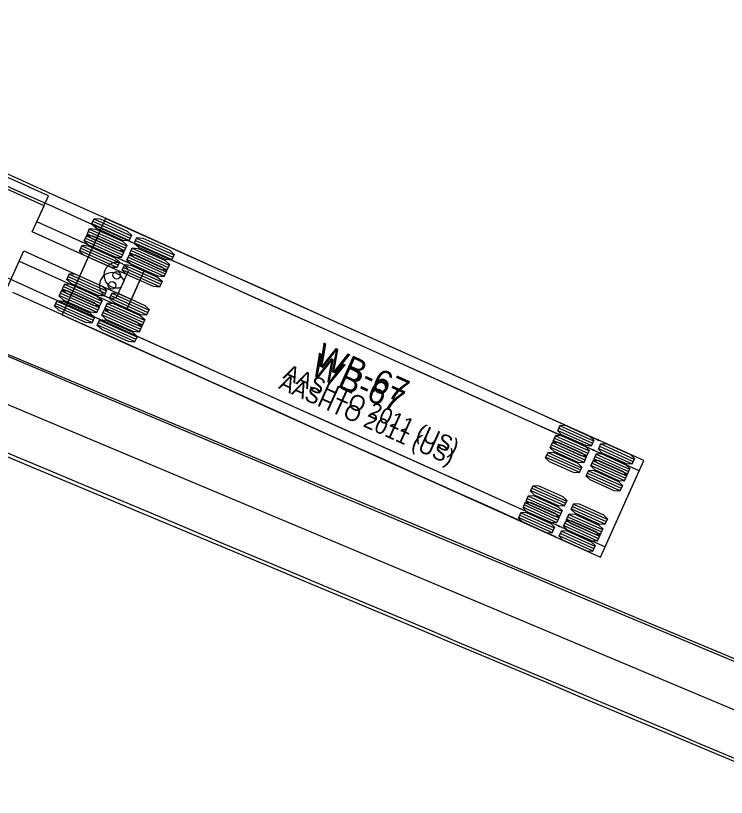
# Model space of a CAD drawing. Extents: x 916040 to 917457, y 328936 to 330267.
# Drawn here: x 917146.2 to 917210, y 329502 to 329572.2 of the extents above; entities that cross this region are included whole.
import ezdxf

# ---------------------------------------------------------------- set-up
doc = ezdxf.new("R2010")
doc.units = 0
for name, color, linetype in [('NB_RightontoRoute25_WB67', 7, 'Continuous'), ('NB_ThruontoManchester_WB67', 7, 'Continuous'), ('WB_LeftontoSaco_WB67', 7, 'Continuous'), ('WB_RightontoManchester_WB67', 7, 'Continuous'), ('WB_Thru_WB67', 7, 'Continuous')]:
    doc.layers.add(name, color=color, linetype=linetype)

msp = doc.modelspace()

# ---------------------------------------------------------------- linework, layer by layer
at = {"layer": 'NB_RightontoRoute25_WB67'}
msp.add_line((917062.28, 329572.242), (917451.537, 329408.712), dxfattribs=at)
for points in [[(917143.156, 329542.604), (917146.231, 329541.313), (917149.306, 329540.021), (917152.38, 329538.729), (917155.455, 329537.437), (917158.53, 329536.146), (917161.604, 329534.854), (917164.679, 329533.562), (917167.754, 329532.271), (917170.829, 329530.979), (917173.903, 329529.687), (917176.978, 329528.395), (917180.053, 329527.104), (917183.128, 329525.812), (917186.202, 329524.52), (917189.277, 329523.229), (917192.352, 329521.937), (917195.426, 329520.645), (917198.501, 329519.353), (917201.576, 329518.062), (917204.651, 329516.77), (917207.725, 329515.478), (917210.8, 329514.187)], [(917144.777, 329542.093), (917147.854, 329540.807), (917150.932, 329539.521), (917154.009, 329538.234), (917157.087, 329536.947), (917160.164, 329535.66), (917163.24, 329534.372), (917166.317, 329533.084), (917169.394, 329531.796), (917172.47, 329530.508), (917175.547, 329529.219), (917178.623, 329527.93), (917181.699, 329526.641), (917184.775, 329525.352), (917187.851, 329524.062), (917190.927, 329522.773), (917194.002, 329521.483), (917197.078, 329520.193), (917200.154, 329518.903), (917203.229, 329517.613), (917206.305, 329516.323), (917209.38, 329515.032), (917212.455, 329513.742)], [(917143.133, 329533.937), (917146.208, 329532.645), (917149.282, 329531.353), (917152.357, 329530.062), (917155.432, 329528.77), (917158.506, 329527.478), (917161.581, 329526.187), (917164.656, 329524.895), (917167.73, 329523.603), (917170.805, 329522.311), (917173.88, 329521.02), (917176.954, 329519.728), (917180.029, 329518.436), (917183.104, 329517.145), (917186.179, 329515.853), (917189.253, 329514.561), (917192.328, 329513.27), (917195.403, 329511.978), (917198.477, 329510.686), (917201.552, 329509.394), (917204.627, 329508.103), (917207.701, 329506.811), (917210.776, 329505.519)], [(917144.577, 329532.964), (917147.654, 329531.679), (917150.73, 329530.392), (917153.806, 329529.106), (917156.883, 329527.819), (917159.959, 329526.531), (917163.035, 329525.244), (917166.111, 329523.956), (917169.186, 329522.668), (917172.262, 329521.379), (917175.338, 329520.091), (917178.413, 329518.802), (917181.489, 329517.513), (917184.564, 329516.223), (917187.64, 329514.934), (917190.715, 329513.644), (917193.79, 329512.355), (917196.866, 329511.065), (917199.941, 329509.775), (917203.016, 329508.485), (917206.091, 329507.194), (917209.166, 329505.904), (917212.242, 329504.614)]]:
    msp.add_lwpolyline(points, dxfattribs=at)
at = {"layer": 'NB_ThruontoManchester_WB67'}
msp.add_line((917062.28, 329572.242), (917451.537, 329408.712), dxfattribs=at)
at = {"layer": 'WB_LeftontoSaco_WB67'}
for p, q in [((917148.719, 329555.149), (917135.042, 329561.308)), ((917147.665, 329552.809), (917148.719, 329555.149)), ((917157.33, 329548.457), (917147.665, 329552.809)), ((917153.837, 329553.119), (917150.347, 329545.368)), ((917152.601, 329552.647), (917155.944, 329551.142)), ((917152.695, 329552.856), (917156.038, 329551.351)), ((917152.789, 329553.065), (917156.132, 329551.56)), ((917202.163, 329531.358), (917153.837, 329553.119)), ((917152.017, 329551.352), (917155.361, 329549.846)), ((917152.111, 329551.561), (917155.455, 329550.055)), ((917156.618, 329551.341), (917159.962, 329549.835)), ((917151.923, 329551.143), (917155.266, 329549.637)), ((917156.43, 329550.923), (917159.774, 329549.417)), ((917156.524, 329551.132), (917159.868, 329549.626)), ((917145.434, 329547.855), (917146.488, 329550.195)), ((917146.488, 329550.195), (917156.153, 329545.843)), ((917155.941, 329549.836), (917159.284, 329548.331)), ((917155.753, 329549.418), (917159.096, 329547.913)), ((917155.847, 329549.627), (917159.19, 329548.122)), ((917155.232, 329546.943), (917155.896, 329548.417)), ((917156.153, 329545.843), (917157.33, 329548.457)), ((917150.37, 329547.693), (917153.713, 329546.188)), ((917150.464, 329547.902), (917153.807, 329546.397)), ((917150.558, 329548.111), (917153.901, 329546.606)), ((917149.786, 329546.398), (917153.13, 329544.892)), ((917149.88, 329546.606), (917153.224, 329545.101)), ((917154.388, 329546.387), (917157.731, 329544.881)), ((917149.692, 329546.189), (917153.036, 329544.683)), ((917154.199, 329545.969), (917157.543, 329544.463)), ((917154.293, 329546.178), (917157.637, 329544.672)), ((917150.347, 329545.368), (917198.673, 329523.607)), ((917150.347, 329545.368), (917150.347, 329545.368)), ((917153.71, 329544.882), (917157.053, 329543.377)), ((917153.522, 329544.464), (917156.865, 329542.959)), ((917153.616, 329544.673), (917156.959, 329543.168)), ((917194.638, 329534.495), (917197.647, 329533.14)), ((917194.45, 329534.077), (917197.459, 329532.722)), ((917194.544, 329534.286), (917197.553, 329532.931)), ((917193.96, 329532.991), (917196.969, 329531.636)), ((917193.772, 329532.573), (917196.781, 329531.218)), ((917193.866, 329532.782), (917196.875, 329531.427)), ((917198.097, 329532.435), (917201.106, 329531.08)), ((917198.191, 329532.644), (917201.2, 329531.289)), ((917198.285, 329532.853), (917201.294, 329531.498)), ((917197.419, 329530.93), (917200.428, 329529.576)), ((917197.513, 329531.139), (917200.522, 329529.785)), ((917197.608, 329531.348), (917200.617, 329529.993)), ((917198.673, 329523.607), (917202.163, 329531.358)), ((917192.107, 329528.876), (917195.116, 329527.521)), ((917192.202, 329529.085), (917195.211, 329527.73)), ((917192.013, 329528.667), (917195.022, 329527.312)), ((917191.43, 329527.372), (917194.439, 329526.017)), ((917191.524, 329527.581), (917194.533, 329526.226)), ((917195.849, 329527.443), (917198.858, 329526.088)), ((917191.336, 329527.163), (917194.345, 329525.808)), ((917195.661, 329527.025), (917198.67, 329525.67)), ((917195.755, 329527.234), (917198.764, 329525.879)), ((917195.171, 329525.938), (917198.18, 329524.583)), ((917194.983, 329525.52), (917197.992, 329524.165)), ((917195.077, 329525.729), (917198.086, 329524.374))]:
    msp.add_line(p, q, dxfattribs=at)
for points in [[(917198.06, 329533.206), (917195.019, 329534.575), (917191.978, 329535.944), (917188.937, 329537.314), (917185.896, 329538.683), (917182.855, 329540.052), (917179.814, 329541.422), (917176.773, 329542.791), (917173.732, 329544.16), (917170.691, 329545.53), (917167.65, 329546.899), (917164.609, 329548.268), (917161.568, 329549.638), (917158.526, 329551.007), (917155.485, 329552.376), (917152.444, 329553.746), (917149.403, 329555.115), (917146.362, 329556.484), (917143.321, 329557.854)], [(917194.57, 329525.455), (917191.529, 329526.824), (917188.488, 329528.194), (917185.447, 329529.563), (917182.406, 329530.932), (917179.365, 329532.302), (917176.324, 329533.671), (917173.283, 329535.041), (917170.242, 329536.41), (917167.201, 329537.779), (917164.16, 329539.149), (917161.119, 329540.518), (917158.078, 329541.887), (917155.037, 329543.257), (917151.995, 329544.626), (917148.954, 329545.995), (917145.913, 329547.365)]]:
    msp.add_lwpolyline(points, dxfattribs=at)
for points in [[(917152.577, 329552.595), (917152.812, 329553.117), (917153.351, 329553.063), (917155.758, 329551.979), (917156.155, 329551.612), (917155.921, 329551.09), (917155.382, 329551.144), (917152.975, 329552.228)], [(917151.9, 329551.091), (917152.135, 329551.613), (917152.673, 329551.559), (917155.081, 329550.475), (917155.478, 329550.107), (917155.243, 329549.585), (917154.704, 329549.639), (917152.297, 329550.723)], [(917156.407, 329550.871), (917156.642, 329551.393), (917157.181, 329551.339), (917159.588, 329550.255), (917159.985, 329549.887), (917159.75, 329549.366), (917159.211, 329549.419), (917156.804, 329550.503)], [(917155.729, 329549.367), (917155.964, 329549.888), (917156.503, 329549.834), (917158.91, 329548.751), (917159.308, 329548.383), (917159.073, 329547.861), (917158.534, 329547.915), (917156.127, 329548.999)], [(917150.346, 329547.641), (917150.581, 329548.163), (917151.12, 329548.109), (917153.527, 329547.025), (917153.925, 329546.657), (917153.69, 329546.136), (917153.151, 329546.189), (917150.744, 329547.273)], [(917149.669, 329546.137), (917149.904, 329546.658), (917150.443, 329546.605), (917152.85, 329545.521), (917153.247, 329545.153), (917153.012, 329544.631), (917152.473, 329544.685), (917150.066, 329545.769)], [(917154.176, 329545.917), (917154.411, 329546.438), (917154.95, 329546.385), (917157.357, 329545.301), (917157.754, 329544.933), (917157.519, 329544.411), (917156.981, 329544.465), (917154.573, 329545.549)], [(917153.499, 329544.412), (917153.733, 329544.934), (917154.272, 329544.88), (917156.679, 329543.796), (917157.077, 329543.428), (917156.842, 329542.907), (917156.303, 329542.96), (917153.896, 329544.044)], [(917194.426, 329534.026), (917194.661, 329534.547), (917195.153, 329534.515), (917197.32, 329533.539), (917197.67, 329533.192), (917197.435, 329532.671), (917196.943, 329532.703), (917194.777, 329533.679)], [(917193.749, 329532.521), (917193.984, 329533.043), (917194.476, 329533.01), (917196.642, 329532.034), (917196.993, 329531.688), (917196.758, 329531.166), (917196.266, 329531.199), (917194.099, 329532.174)], [(917198.073, 329532.383), (917198.308, 329532.905), (917198.8, 329532.872), (917200.967, 329531.897), (917201.317, 329531.55), (917201.082, 329531.028), (917200.59, 329531.061), (917198.424, 329532.036)], [(917197.396, 329530.879), (917197.631, 329531.4), (917198.123, 329531.368), (917200.289, 329530.392), (917200.64, 329530.045), (917200.405, 329529.524), (917199.913, 329529.556), (917197.747, 329530.532)], [(917191.99, 329528.615), (917192.225, 329529.137), (917192.717, 329529.104), (917194.883, 329528.129), (917195.234, 329527.782), (917194.999, 329527.26), (917194.507, 329527.293), (917192.341, 329528.269)], [(917191.313, 329527.111), (917191.547, 329527.632), (917192.039, 329527.6), (917194.206, 329526.624), (917194.556, 329526.277), (917194.322, 329525.756), (917193.83, 329525.788), (917191.663, 329526.764)], [(917195.637, 329526.973), (917195.872, 329527.495), (917196.364, 329527.462), (917198.531, 329526.486), (917198.881, 329526.14), (917198.646, 329525.618), (917198.154, 329525.651), (917195.988, 329526.626)], [(917194.96, 329525.469), (917195.195, 329525.99), (917195.687, 329525.958), (917197.853, 329524.982), (917198.204, 329524.635), (917197.969, 329524.114), (917197.477, 329524.146), (917195.31, 329525.122)]]:
    msp.add_lwpolyline(points, close=True, dxfattribs=at)
for centre, radius in [((917154.827, 329548.012), 0.34), ((917198.06, 329533.206), 0.0417), ((917194.57, 329525.455), 0.0417)]:
    msp.add_circle(centre, radius, dxfattribs=at)
msp.add_arc((917154.827, 329548.012), 1.143, 20.75845, 290.75845, dxfattribs=at)
at = {"layer": 'WB_RightontoManchester_WB67'}
for p, q in [((917149.129, 329556.061), (917135.452, 329562.22)), ((917148.076, 329553.721), (917149.129, 329556.061)), ((917154.247, 329554.031), (917150.757, 329546.28)), ((917153.199, 329553.977), (917156.543, 329552.472)), ((917202.574, 329532.27), (917154.247, 329554.031)), ((917157.741, 329549.368), (917148.076, 329553.721)), ((917153.011, 329553.559), (917156.355, 329552.054)), ((917153.105, 329553.768), (917156.449, 329552.263)), ((917152.334, 329552.055), (917155.677, 329550.549)), ((917152.428, 329552.264), (917155.771, 329550.758)), ((917152.522, 329552.473), (917155.865, 329550.967)), ((917156.935, 329552.044), (917160.278, 329550.538)), ((917157.029, 329552.253), (917160.372, 329550.747)), ((917156.841, 329551.835), (917160.184, 329550.329)), ((917145.845, 329548.766), (917146.899, 329551.107)), ((917146.899, 329551.107), (917156.564, 329546.755)), ((917156.257, 329550.539), (917159.601, 329549.034)), ((917156.352, 329550.748), (917159.695, 329549.243)), ((917156.163, 329550.33), (917159.507, 329548.825)), ((917155.643, 329547.855), (917156.306, 329549.329)), ((917156.564, 329546.755), (917157.741, 329549.368)), ((917150.78, 329548.605), (917154.124, 329547.099)), ((917150.874, 329548.814), (917154.218, 329547.308)), ((917150.969, 329549.023), (917154.312, 329547.517)), ((917150.103, 329547.1), (917153.446, 329545.595)), ((917150.197, 329547.309), (917153.54, 329545.804)), ((917150.291, 329547.518), (917153.634, 329546.013)), ((917154.704, 329547.089), (917158.047, 329545.584)), ((917154.798, 329547.298), (917158.142, 329545.793)), ((917150.757, 329546.28), (917199.084, 329524.519)), ((917150.757, 329546.28), (917150.757, 329546.28)), ((917154.61, 329546.88), (917157.953, 329545.375)), ((917154.027, 329545.585), (917157.37, 329544.079)), ((917154.121, 329545.794), (917157.464, 329544.288)), ((917153.933, 329545.376), (917157.276, 329543.87)), ((917194.954, 329535.198), (917197.963, 329533.843)), ((917195.048, 329535.407), (917198.057, 329534.052)), ((917194.86, 329534.989), (917197.869, 329533.634)), ((917194.277, 329533.694), (917197.286, 329532.339)), ((917194.371, 329533.903), (917197.38, 329532.548)), ((917198.696, 329533.765), (917201.705, 329532.41)), ((917194.183, 329533.485), (917197.192, 329532.13)), ((917198.507, 329533.347), (917201.516, 329531.992)), ((917198.601, 329533.556), (917201.61, 329532.201)), ((917198.018, 329532.26), (917201.027, 329530.905)), ((917199.084, 329524.519), (917202.574, 329532.27)), ((917197.83, 329531.842), (917200.839, 329530.487)), ((917197.924, 329532.051), (917200.933, 329530.696)), ((917192.424, 329529.579), (917195.433, 329528.224)), ((917192.518, 329529.788), (917195.527, 329528.433)), ((917192.612, 329529.997), (917195.621, 329528.642)), ((917191.747, 329528.074), (917194.756, 329526.72)), ((917191.841, 329528.283), (917194.85, 329526.929)), ((917191.935, 329528.492), (917194.944, 329527.137)), ((917196.165, 329528.146), (917199.174, 329526.791)), ((917196.259, 329528.355), (917199.268, 329527)), ((917196.071, 329527.937), (917199.08, 329526.582)), ((917195.488, 329526.641), (917198.497, 329525.286)), ((917195.582, 329526.85), (917198.591, 329525.495)), ((917195.394, 329526.432), (917198.403, 329525.077))]:
    msp.add_line(p, q, dxfattribs=at)
for points in [[(917198.471, 329534.117), (917195.429, 329535.487), (917192.388, 329536.856), (917189.347, 329538.225), (917186.306, 329539.595), (917183.265, 329540.964), (917180.224, 329542.333), (917177.183, 329543.703), (917174.142, 329545.072), (917171.101, 329546.442), (917168.06, 329547.811), (917165.019, 329549.18), (917161.978, 329550.55), (917158.937, 329551.919), (917155.896, 329553.288), (917152.855, 329554.658), (917149.814, 329556.027), (917146.773, 329557.396), (917143.732, 329558.766)], [(917194.981, 329526.367), (917191.94, 329527.736), (917188.898, 329529.106), (917185.857, 329530.475), (917182.816, 329531.844), (917179.775, 329533.214), (917176.734, 329534.583), (917173.693, 329535.952), (917170.652, 329537.322), (917167.611, 329538.691), (917164.57, 329540.06), (917161.529, 329541.43), (917158.488, 329542.799), (917155.447, 329544.168), (917152.406, 329545.538), (917149.365, 329546.907), (917146.324, 329548.276), (917143.283, 329549.646)]]:
    msp.add_lwpolyline(points, dxfattribs=at)
for points in [[(917152.988, 329553.507), (917153.223, 329554.029), (917153.762, 329553.975), (917156.169, 329552.891), (917156.566, 329552.523), (917156.331, 329552.002), (917155.792, 329552.055), (917153.385, 329553.139)], [(917152.31, 329552.003), (917152.545, 329552.524), (917153.084, 329552.471), (917155.491, 329551.387), (917155.889, 329551.019), (917155.654, 329550.497), (917155.115, 329550.551), (917152.708, 329551.635)], [(917156.817, 329551.783), (917157.052, 329552.304), (917157.591, 329552.251), (917159.998, 329551.167), (917160.396, 329550.799), (917160.161, 329550.277), (917159.622, 329550.331), (917157.215, 329551.415)], [(917156.14, 329550.278), (917156.375, 329550.8), (917156.914, 329550.746), (917159.321, 329549.662), (917159.718, 329549.294), (917159.483, 329548.773), (917158.945, 329548.826), (917156.537, 329549.91)], [(917150.757, 329548.553), (917150.992, 329549.075), (917151.531, 329549.021), (917153.938, 329547.937), (917154.335, 329547.569), (917154.1, 329547.048), (917153.562, 329547.101), (917151.154, 329548.185)], [(917150.08, 329547.049), (917150.314, 329547.57), (917150.853, 329547.516), (917153.26, 329546.433), (917153.658, 329546.065), (917153.423, 329545.543), (917152.884, 329545.597), (917150.477, 329546.681)], [(917154.587, 329546.829), (917154.822, 329547.35), (917155.36, 329547.297), (917157.768, 329546.213), (917158.165, 329545.845), (917157.93, 329545.323), (917157.391, 329545.377), (917154.984, 329546.461)], [(917153.909, 329545.324), (917154.144, 329545.846), (917154.683, 329545.792), (917157.09, 329544.708), (917157.487, 329544.34), (917157.253, 329543.819), (917156.714, 329543.872), (917154.307, 329544.956)], [(917194.837, 329534.937), (917195.072, 329535.459), (917195.564, 329535.426), (917197.73, 329534.451), (917198.081, 329534.104), (917197.846, 329533.582), (917197.354, 329533.615), (917195.187, 329534.591)], [(917194.159, 329533.433), (917194.394, 329533.954), (917194.886, 329533.922), (917197.053, 329532.946), (917197.403, 329532.599), (917197.168, 329532.078), (917196.676, 329532.11), (917194.51, 329533.086)], [(917198.484, 329533.295), (917198.719, 329533.817), (917199.211, 329533.784), (917201.377, 329532.808), (917201.728, 329532.462), (917201.493, 329531.94), (917201.001, 329531.973), (917198.835, 329532.948)], [(917197.807, 329531.79), (917198.041, 329532.312), (917198.533, 329532.279), (917200.7, 329531.304), (917201.05, 329530.957), (917200.816, 329530.436), (917200.324, 329530.468), (917198.157, 329531.444)], [(917192.401, 329529.527), (917192.635, 329530.049), (917193.128, 329530.016), (917195.294, 329529.041), (917195.645, 329528.694), (917195.41, 329528.172), (917194.918, 329528.205), (917192.751, 329529.18)], [(917191.723, 329528.023), (917191.958, 329528.544), (917192.45, 329528.512), (917194.617, 329527.536), (917194.967, 329527.189), (917194.732, 329526.668), (917194.24, 329526.7), (917192.074, 329527.676)], [(917196.048, 329527.885), (917196.283, 329528.406), (917196.775, 329528.374), (917198.941, 329527.398), (917199.292, 329527.051), (917199.057, 329526.53), (917198.565, 329526.562), (917196.398, 329527.538)], [(917195.37, 329526.38), (917195.605, 329526.902), (917196.097, 329526.869), (917198.264, 329525.894), (917198.614, 329525.547), (917198.379, 329525.025), (917197.887, 329525.058), (917195.721, 329526.034)]]:
    msp.add_lwpolyline(points, close=True, dxfattribs=at)
for centre, radius in [((917155.238, 329548.924), 0.34), ((917198.471, 329534.117), 0.0417), ((917194.981, 329526.367), 0.0417)]:
    msp.add_circle(centre, radius, dxfattribs=at)
msp.add_arc((917155.238, 329548.924), 1.143, 20.75845, 290.75845, dxfattribs=at)
at = {"layer": 'WB_Thru_WB67'}
for p, q in [((917148.719, 329555.149), (917135.042, 329561.308)), ((917147.665, 329552.809), (917148.719, 329555.149)), ((917157.33, 329548.457), (917147.665, 329552.809)), ((917153.837, 329553.119), (917150.347, 329545.368)), ((917152.601, 329552.647), (917155.944, 329551.142)), ((917152.695, 329552.856), (917156.038, 329551.351)), ((917152.789, 329553.065), (917156.132, 329551.56)), ((917202.163, 329531.358), (917153.837, 329553.119)), ((917152.017, 329551.352), (917155.361, 329549.846)), ((917152.111, 329551.561), (917155.455, 329550.055)), ((917156.618, 329551.341), (917159.962, 329549.835)), ((917151.923, 329551.143), (917155.266, 329549.637)), ((917156.43, 329550.923), (917159.774, 329549.417)), ((917156.524, 329551.132), (917159.868, 329549.626)), ((917145.434, 329547.855), (917146.488, 329550.195)), ((917146.488, 329550.195), (917156.153, 329545.843)), ((917155.941, 329549.836), (917159.284, 329548.331)), ((917155.753, 329549.418), (917159.096, 329547.913)), ((917155.847, 329549.627), (917159.19, 329548.122)), ((917155.232, 329546.943), (917155.896, 329548.417)), ((917156.153, 329545.843), (917157.33, 329548.457)), ((917150.37, 329547.693), (917153.713, 329546.188)), ((917150.464, 329547.902), (917153.807, 329546.397)), ((917150.558, 329548.111), (917153.901, 329546.606)), ((917149.786, 329546.398), (917153.13, 329544.892)), ((917149.88, 329546.606), (917153.224, 329545.101)), ((917154.388, 329546.387), (917157.731, 329544.881)), ((917149.692, 329546.189), (917153.036, 329544.683)), ((917154.199, 329545.969), (917157.543, 329544.463)), ((917154.293, 329546.178), (917157.637, 329544.672)), ((917150.347, 329545.368), (917198.673, 329523.607)), ((917150.347, 329545.368), (917150.347, 329545.368)), ((917153.71, 329544.882), (917157.053, 329543.377)), ((917153.522, 329544.464), (917156.865, 329542.959)), ((917153.616, 329544.673), (917156.959, 329543.168)), ((917194.638, 329534.495), (917197.647, 329533.14)), ((917194.45, 329534.077), (917197.459, 329532.722)), ((917194.544, 329534.286), (917197.553, 329532.931)), ((917193.96, 329532.991), (917196.969, 329531.636)), ((917193.772, 329532.573), (917196.781, 329531.218)), ((917193.866, 329532.782), (917196.875, 329531.427)), ((917198.097, 329532.435), (917201.106, 329531.08)), ((917198.191, 329532.644), (917201.2, 329531.289)), ((917198.285, 329532.853), (917201.294, 329531.498)), ((917197.419, 329530.93), (917200.428, 329529.576)), ((917197.513, 329531.139), (917200.522, 329529.785)), ((917197.608, 329531.348), (917200.617, 329529.993)), ((917198.673, 329523.607), (917202.163, 329531.358)), ((917192.107, 329528.876), (917195.116, 329527.521)), ((917192.202, 329529.085), (917195.211, 329527.73)), ((917192.013, 329528.667), (917195.022, 329527.312)), ((917191.43, 329527.372), (917194.439, 329526.017)), ((917191.524, 329527.581), (917194.533, 329526.226)), ((917195.849, 329527.443), (917198.858, 329526.088)), ((917191.336, 329527.163), (917194.345, 329525.808)), ((917195.661, 329527.025), (917198.67, 329525.67)), ((917195.755, 329527.234), (917198.764, 329525.879)), ((917195.171, 329525.938), (917198.18, 329524.583)), ((917194.983, 329525.52), (917197.992, 329524.165)), ((917195.077, 329525.729), (917198.086, 329524.374))]:
    msp.add_line(p, q, dxfattribs=at)
for points in [[(917198.06, 329533.206), (917195.019, 329534.575), (917191.978, 329535.944), (917188.937, 329537.314), (917185.896, 329538.683), (917182.855, 329540.052), (917179.814, 329541.422), (917176.773, 329542.791), (917173.732, 329544.16), (917170.691, 329545.53), (917167.65, 329546.899), (917164.609, 329548.268), (917161.568, 329549.638), (917158.526, 329551.007), (917155.485, 329552.376), (917152.444, 329553.746), (917149.403, 329555.115), (917146.362, 329556.484), (917143.321, 329557.854)], [(917194.57, 329525.455), (917191.529, 329526.824), (917188.488, 329528.194), (917185.447, 329529.563), (917182.406, 329530.932), (917179.365, 329532.302), (917176.324, 329533.671), (917173.283, 329535.041), (917170.242, 329536.41), (917167.201, 329537.779), (917164.16, 329539.149), (917161.119, 329540.518), (917158.078, 329541.887), (917155.037, 329543.257), (917151.995, 329544.626), (917148.954, 329545.995), (917145.913, 329547.365)]]:
    msp.add_lwpolyline(points, dxfattribs=at)
for points in [[(917152.577, 329552.595), (917152.812, 329553.117), (917153.351, 329553.063), (917155.758, 329551.979), (917156.155, 329551.612), (917155.921, 329551.09), (917155.382, 329551.144), (917152.975, 329552.228)], [(917151.9, 329551.091), (917152.135, 329551.613), (917152.673, 329551.559), (917155.081, 329550.475), (917155.478, 329550.107), (917155.243, 329549.585), (917154.704, 329549.639), (917152.297, 329550.723)], [(917156.407, 329550.871), (917156.642, 329551.393), (917157.181, 329551.339), (917159.588, 329550.255), (917159.985, 329549.887), (917159.75, 329549.366), (917159.211, 329549.419), (917156.804, 329550.503)], [(917155.729, 329549.367), (917155.964, 329549.888), (917156.503, 329549.834), (917158.91, 329548.751), (917159.308, 329548.383), (917159.073, 329547.861), (917158.534, 329547.915), (917156.127, 329548.999)], [(917150.346, 329547.641), (917150.581, 329548.163), (917151.12, 329548.109), (917153.527, 329547.025), (917153.925, 329546.657), (917153.69, 329546.136), (917153.151, 329546.189), (917150.744, 329547.273)], [(917149.669, 329546.137), (917149.904, 329546.658), (917150.443, 329546.605), (917152.85, 329545.521), (917153.247, 329545.153), (917153.012, 329544.631), (917152.473, 329544.685), (917150.066, 329545.769)], [(917154.176, 329545.917), (917154.411, 329546.438), (917154.95, 329546.385), (917157.357, 329545.301), (917157.754, 329544.933), (917157.519, 329544.411), (917156.981, 329544.465), (917154.573, 329545.549)], [(917153.499, 329544.412), (917153.733, 329544.934), (917154.272, 329544.88), (917156.679, 329543.796), (917157.077, 329543.428), (917156.842, 329542.907), (917156.303, 329542.96), (917153.896, 329544.044)], [(917194.426, 329534.026), (917194.661, 329534.547), (917195.153, 329534.515), (917197.32, 329533.539), (917197.67, 329533.192), (917197.435, 329532.671), (917196.943, 329532.703), (917194.777, 329533.679)], [(917193.749, 329532.521), (917193.984, 329533.043), (917194.476, 329533.01), (917196.642, 329532.034), (917196.993, 329531.688), (917196.758, 329531.166), (917196.266, 329531.199), (917194.099, 329532.174)], [(917198.073, 329532.383), (917198.308, 329532.905), (917198.8, 329532.872), (917200.967, 329531.897), (917201.317, 329531.55), (917201.082, 329531.028), (917200.59, 329531.061), (917198.424, 329532.036)], [(917197.396, 329530.879), (917197.631, 329531.4), (917198.123, 329531.368), (917200.289, 329530.392), (917200.64, 329530.045), (917200.405, 329529.524), (917199.913, 329529.556), (917197.747, 329530.532)], [(917191.99, 329528.615), (917192.225, 329529.137), (917192.717, 329529.104), (917194.883, 329528.129), (917195.234, 329527.782), (917194.999, 329527.26), (917194.507, 329527.293), (917192.341, 329528.269)], [(917191.313, 329527.111), (917191.547, 329527.632), (917192.039, 329527.6), (917194.206, 329526.624), (917194.556, 329526.277), (917194.322, 329525.756), (917193.83, 329525.788), (917191.663, 329526.764)], [(917195.637, 329526.973), (917195.872, 329527.495), (917196.364, 329527.462), (917198.531, 329526.486), (917198.881, 329526.14), (917198.646, 329525.618), (917198.154, 329525.651), (917195.988, 329526.626)], [(917194.96, 329525.469), (917195.195, 329525.99), (917195.687, 329525.958), (917197.853, 329524.982), (917198.204, 329524.635), (917197.969, 329524.114), (917197.477, 329524.146), (917195.31, 329525.122)]]:
    msp.add_lwpolyline(points, close=True, dxfattribs=at)
for centre, radius in [((917154.827, 329548.012), 0.34), ((917198.06, 329533.206), 0.0417), ((917194.57, 329525.455), 0.0417)]:
    msp.add_circle(centre, radius, dxfattribs=at)
msp.add_arc((917154.827, 329548.012), 1.143, 20.75845, 290.75845, dxfattribs=at)

# ---------------------------------------------------------------- texts
at = {"layer": 'WB_LeftontoSaco_WB67'}
for s, height, p in [('WB-67', 2.125, (917172.518, 329540.046)), ('AASHTO 2011 (US)', 1.41667, (917169.7, 329538.79))]:
    msp.add_text(s, height=height, rotation=335.75845, dxfattribs=at).set_placement(p)
at = {"layer": 'WB_RightontoManchester_WB67'}
for s, height, p in [('WB-67', 2.125, (917172.929, 329540.958)), ('AASHTO 2011 (US)', 1.41667, (917170.111, 329539.702))]:
    msp.add_text(s, height=height, rotation=335.75845, dxfattribs=at).set_placement(p)
at = {"layer": 'WB_Thru_WB67'}
for s, height, p in [('WB-67', 2.125, (917172.518, 329540.046)), ('AASHTO 2011 (US)', 1.41667, (917169.7, 329538.79))]:
    msp.add_text(s, height=height, rotation=335.75845, dxfattribs=at).set_placement(p)

doc.saveas('drawing.dxf')
